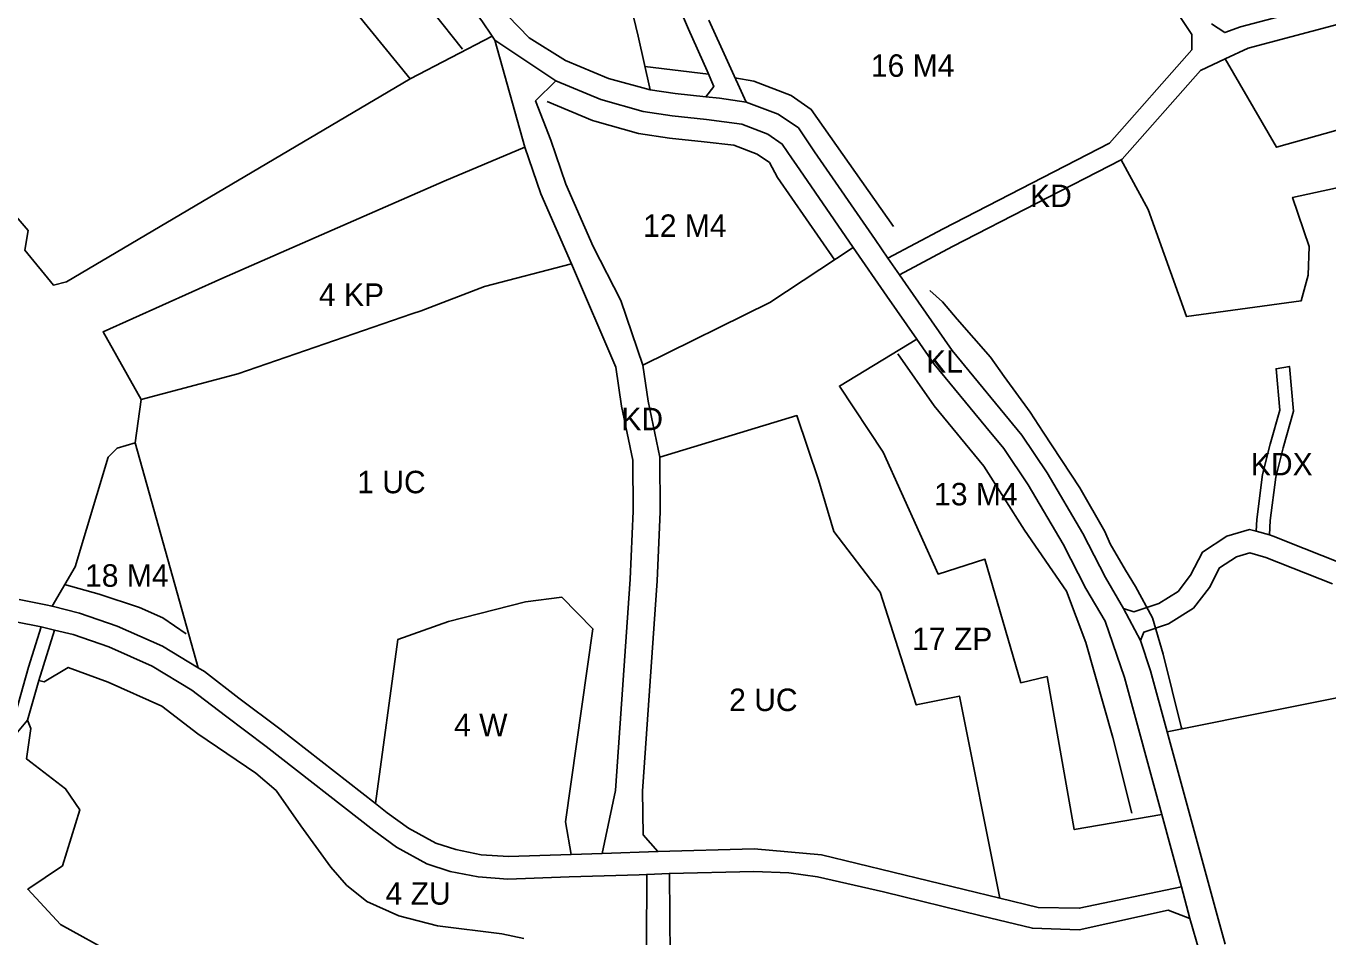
# Model space of a CAD drawing. Extents: x 7437831 to 7440315, y 5545798 to 5547888.
# Drawn here: x 7439385 to 7439964, y 5546851 to 5547256 of the extents above; entities that cross this region are included whole.
import ezdxf

# ---------------------------------------------------------------- set-up
doc = ezdxf.new("R2010")
doc.units = 0
for name, color, linetype in [('linie_rozgraniczajace', 7, 'Continuous'), ('linie_zabudowy_nieprzekraczalne', 7, 'Continuous'), ('oznaczenia_przeznaczen', 7, 'Continuous')]:
    doc.layers.add(name, color=color, linetype=linetype)

msp = doc.modelspace()

# ---------------------------------------------------------------- linework, layer by layer
at = {"layer": 'linie_rozgraniczajace'}
for points in [[(7439721.65, 5547203.82), (7439715.2, 5547208.23), (7439703.63, 5547212.64), (7439687.89, 5547214.81), (7439672.7, 5547216.33), (7439659.7, 5547218.31), (7439640.95, 5547223.59), (7439620.79, 5547231.98), (7439593.65, 5547250.12), (7439592.45, 5547251.78), (7439587.97, 5547258.66), (7439572.92, 5547278.45), (7439537.42, 5547327.35), (7439521.84, 5547350.29), (7439476.68, 5547412.41), (7439450.29, 5547445.41), (7439431.75, 5547471.05), (7439420.51, 5547489.6), (7439410.65, 5547514.06), (7439404.34, 5547535.78), (7439402.31, 5547543.75), (7439398.38, 5547559.18), (7439395.54, 5547573.5), (7439401.86, 5547591.35)], [(7439640.75, 5547321.64), (7439657.53, 5547251.88), (7439662.79, 5547227.95), (7439644.24, 5547233.06), (7439625.08, 5547241.02), (7439608.97, 5547251.12), (7439599.56, 5547260.93)], [(7439671.52, 5547274.57), (7439679.85, 5547254.99), (7439688.17, 5547236.45), (7439691.12, 5547229.44), (7439687.54, 5547224.9), (7439673.95, 5547226.25), (7439662.79, 5547227.95), (7439657.53, 5547251.88), (7439640.75, 5547321.64)], [(7439689.01, 5547258.99), (7439705.56, 5547222.46), (7439693.72, 5547224.28), (7439687.54, 5547224.9), (7439691.12, 5547229.44), (7439688.17, 5547236.45), (7439679.85, 5547254.99), (7439671.52, 5547274.57)], [(7439891.86, 5547270.85), (7439903.96, 5547252.55), (7439903.9, 5547245.77), (7439867.23, 5547204.26), (7439793.21, 5547166.14), (7439768.63, 5547153.08), (7439762.91, 5547161.37), (7439736.04, 5547200.29), (7439728.88, 5547210.98), (7439719.87, 5547217.15), (7439705.56, 5547222.46), (7439689.01, 5547258.99)], [(7439997.61, 5547264.78), (7439929.04, 5547246.52), (7439918.81, 5547241.72), (7439907.74, 5547236.53), (7439872.86, 5547197.03), (7439872.49, 5547196.85), (7439797.39, 5547158.17), (7439773.78, 5547145.63), (7439768.63, 5547153.08), (7439793.21, 5547166.14), (7439867.23, 5547204.26), (7439903.9, 5547245.77), (7439903.96, 5547252.55), (7439891.86, 5547270.85)], [(7439995.02, 5547274.44), (7439925.61, 5547255.95), (7439918.53, 5547253.45), (7439912.61, 5547257.28)], [(7439912.61, 5547257.28), (7439918.53, 5547253.45), (7439925.61, 5547255.95), (7439995.02, 5547274.44)], [(7439994.44, 5547217.29), (7439941.63, 5547202.42), (7439918.81, 5547241.72), (7439929.04, 5547246.52), (7439997.61, 5547264.78)], [(7439599.56, 5547260.93), (7439608.97, 5547251.12), (7439625.08, 5547241.02), (7439644.24, 5547233.06), (7439662.79, 5547227.95), (7439673.95, 5547226.25), (7439687.54, 5547224.9), (7439693.72, 5547224.28), (7439705.56, 5547222.46), (7439719.87, 5547217.15), (7439728.88, 5547210.98), (7439736.04, 5547200.29), (7439762.91, 5547161.37), (7439768.63, 5547153.08), (7439773.78, 5547145.63), (7439776.44, 5547141.77), (7439797.25, 5547111.91), (7439828.22, 5547074.28), (7439839.5, 5547057.41), (7439855.38, 5547030.53), (7439865.48, 5547010.81), (7439873.54, 5546997.1), (7439881.01, 5546982.86), (7439885.5, 5546969.4), (7439892.92, 5546942.17), (7439915.58, 5546858.94), (7439918.8, 5546847.65)], [(7439368.08, 5547186.09), (7439386.01, 5547165.4), (7439384.59, 5547156.64), (7439397.35, 5547140.99), (7439403.12, 5547142.44), (7439556.07, 5547232.92), (7439592.45, 5547251.78), (7439593.65, 5547250.12), (7439606.98, 5547202.45), (7439571.14, 5547187.31), (7439521.23, 5547165.56), (7439472.15, 5547143.97), (7439419.37, 5547120.24), (7439436.36, 5547090.06), (7439433.56, 5547070.86), (7439425.57, 5547068.38), (7439421.68, 5547064.4), (7439406.97, 5547015.65), (7439396.67, 5546998.07), (7439393.87, 5546998.67), (7439382.07, 5547001.08)], [(7440059.38, 5547204.07), (7439948.78, 5547180.1), (7439956.16, 5547158.18), (7439955.68, 5547145.43), (7439952.64, 5547134.07), (7439901.52, 5547127), (7439884.54, 5547174.62), (7439872.49, 5547196.85), (7439872.86, 5547197.03), (7439907.74, 5547236.53), (7439918.81, 5547241.72), (7439941.63, 5547202.42), (7439994.44, 5547217.29)], [(7439907.31, 5546844.22), (7439903.09, 5546859.16), (7439899.28, 5546873.14), (7439890.52, 5546905.32), (7439873.9, 5546966.35), (7439865.29, 5546991.42), (7439856.71, 5547005.99), (7439846.62, 5547025.71), (7439831.04, 5547052.09), (7439820.19, 5547068.29), (7439812.18, 5547077.96), (7439789.27, 5547105.87), (7439781.57, 5547116.92), (7439768.22, 5547136.07), (7439753.22, 5547157.81), (7439727.77, 5547194.66), (7439726.04, 5547197.26), (7439721.65, 5547203.82)], [(7439969.62, 5547017.51), (7439953.87, 5547023.73), (7439940.11, 5547029.33), (7439938.41, 5547029.81), (7439938.83, 5547036.19), (7439941.23, 5547055.55), (7439944.61, 5547068.63), (7439949.1, 5547084.88), (7439947.31, 5547104.81), (7439941.38, 5547103.8), (7439943.03, 5547085.43), (7439938.81, 5547070.17), (7439935.33, 5547056.67), (7439932.86, 5547036.76), (7439932.5, 5547031.45), (7439929.55, 5547032.27), (7439919.55, 5547029.25), (7439908.63, 5547022.19), (7439903.33, 5547011.86), (7439897.78, 5547004.72), (7439889.26, 5546999.35), (7439878.13, 5546995.63), (7439873.54, 5546997.1), (7439865.48, 5547010.81), (7439855.38, 5547030.53), (7439839.5, 5547057.41), (7439828.22, 5547074.28), (7439797.25, 5547111.91), (7439776.44, 5547141.77), (7439773.78, 5547145.63), (7439797.39, 5547158.17), (7439872.49, 5547196.85), (7439884.54, 5547174.62), (7439901.52, 5547127), (7439952.64, 5547134.07), (7439955.68, 5547145.43), (7439956.16, 5547158.18), (7439948.78, 5547180.1), (7440059.38, 5547204.07)], [(7439966.48, 5547007.99), (7439936.88, 5547019.85), (7439929.67, 5547021.86), (7439923.79, 5547020.08), (7439916.3, 5547015.24), (7439911.8, 5547006.46), (7439904.59, 5546997.2), (7439893.58, 5546990.24), (7439882.62, 5546986.58), (7439881.01, 5546982.86), (7439873.54, 5546997.1), (7439878.13, 5546995.63), (7439889.26, 5546999.35), (7439897.78, 5547004.72), (7439903.33, 5547011.86), (7439908.63, 5547022.19), (7439919.55, 5547029.25), (7439929.55, 5547032.27), (7439932.5, 5547031.45), (7439938.41, 5547029.81), (7439940.11, 5547029.33), (7439953.87, 5547023.73), (7439969.62, 5547017.51)], [(7440044.56, 5546972.61), (7439892.92, 5546942.17), (7439885.5, 5546969.4), (7439881.01, 5546982.86), (7439882.62, 5546986.58), (7439893.58, 5546990.24), (7439904.59, 5546997.2), (7439911.8, 5547006.46), (7439916.3, 5547015.24), (7439923.79, 5547020.08), (7439929.67, 5547021.86), (7439936.88, 5547019.85), (7439966.48, 5547007.99)], [(7439382.07, 5547001.08), (7439393.87, 5546998.67), (7439396.67, 5546998.07), (7439408.88, 5546995.06), (7439425.56, 5546989.29), (7439445.77, 5546980.27), (7439461.66, 5546970.72), (7439464.55, 5546968.98), (7439479.81, 5546957.2), (7439498.01, 5546943.52), (7439540.65, 5546910.21), (7439545.83, 5546906.16), (7439555.27, 5546899.25), (7439567.42, 5546892.61), (7439576.35, 5546889.75), (7439587.63, 5546887.5), (7439599.71, 5546886.63), (7439627.65, 5546887.63), (7439641.52, 5546888.06), (7439666.25, 5546888.85), (7439709.13, 5546890.06), (7439739.03, 5546887.5), (7439818.43, 5546868.16), (7439835.56, 5546863.99), (7439853.79, 5546863.67), (7439899.28, 5546873.14), (7439903.09, 5546859.16), (7439893.4, 5546862.8), (7439853.75, 5546854.09), (7439832.98, 5546854.74), (7439810.08, 5546860.26), (7439766.68, 5546871.01), (7439737.25, 5546877.65), (7439724.55, 5546879.39), (7439709.04, 5546880.05), (7439671.37, 5546879.16), (7439661.34, 5546878.71), (7439657.91, 5546878.56), (7439626.85, 5546877.6), (7439599.53, 5546876.62), (7439586.29, 5546877.57), (7439573.84, 5546880.06), (7439563.46, 5546883.38), (7439549.9, 5546890.79), (7439539.8, 5546898.19), (7439491.92, 5546935.58), (7439473.76, 5546949.25), (7439458.9, 5546960.71), (7439441.14, 5546971.38), (7439421.89, 5546979.98), (7439406.07, 5546985.45), (7439397.68, 5546987.47), (7439391.83, 5546988.88), (7439380.51, 5546991.19)], [(7439380.51, 5546991.19), (7439391.83, 5546988.88), (7439386.11, 5546970.9), (7439380.33, 5546950.3)], [(7439380.33, 5546950.3), (7439386.11, 5546970.9), (7439391.83, 5546988.88), (7439397.68, 5546987.47), (7439390.7, 5546965.05), (7439385.76, 5546947.44), (7439381.22, 5546942.02)], [(7439606.57, 5546850.24), (7439596.81, 5546852.25), (7439568.14, 5546855.86), (7439551.02, 5546860.31), (7439536.79, 5546866.66), (7439527.75, 5546873.86), (7439520.72, 5546881.95), (7439507.29, 5546900.3), (7439496.35, 5546916.12), (7439487.36, 5546923.82), (7439461.49, 5546941.3), (7439445.56, 5546953.62), (7439421.54, 5546964.22), (7439403.83, 5546970.85), (7439393.13, 5546964.47), (7439390.7, 5546965.05), (7439397.68, 5546987.47), (7439406.07, 5546985.45), (7439421.89, 5546979.98), (7439441.14, 5546971.38), (7439458.9, 5546960.71), (7439473.76, 5546949.25), (7439491.92, 5546935.58), (7439539.8, 5546898.19), (7439549.9, 5546890.79), (7439563.46, 5546883.38), (7439573.84, 5546880.06), (7439586.29, 5546877.57), (7439599.53, 5546876.62), (7439626.85, 5546877.6), (7439657.91, 5546878.56), (7439661.34, 5546878.71), (7439661, 5546816.56)], [(7439390.7, 5546965.05), (7439393.13, 5546964.47), (7439403.83, 5546970.85), (7439421.54, 5546964.22), (7439445.56, 5546953.62), (7439461.49, 5546941.3), (7439487.36, 5546923.82), (7439496.35, 5546916.12), (7439507.29, 5546900.3), (7439520.72, 5546881.95), (7439527.75, 5546873.86), (7439536.79, 5546866.66), (7439551.02, 5546860.31), (7439568.14, 5546855.86), (7439596.81, 5546852.25), (7439606.57, 5546850.24)], [(7439918.8, 5546847.65), (7439915.58, 5546858.94), (7439892.92, 5546942.17), (7440044.56, 5546972.61)], [(7439486.82, 5546785.36), (7439478.44, 5546804.23), (7439450.21, 5546815.29), (7439431.59, 5546839.56), (7439424.64, 5546843.02), (7439400.36, 5546856.35), (7439385.83, 5546872.11), (7439401.24, 5546882.58), (7439408.98, 5546907.43), (7439402.67, 5546916.88), (7439385.28, 5546930.1), (7439387.21, 5546943.73), (7439385.76, 5546947.44), (7439390.7, 5546965.05)], [(7439381.22, 5546942.02), (7439385.76, 5546947.44), (7439387.21, 5546943.73), (7439385.28, 5546930.1), (7439402.67, 5546916.88), (7439408.98, 5546907.43), (7439401.24, 5546882.58), (7439385.83, 5546872.11), (7439400.36, 5546856.35), (7439424.64, 5546843.02), (7439431.59, 5546839.56), (7439450.21, 5546815.29), (7439478.44, 5546804.23), (7439486.82, 5546785.36), (7439486.23, 5546779.85), (7439466.03, 5546783.83), (7439443.54, 5546786.77), (7439407.4, 5546817.11), (7439388.08, 5546823.63), (7439382.15, 5546831.69)], [(7439661, 5546816.56), (7439661.34, 5546878.71), (7439671.37, 5546879.16), (7439671.77, 5546841.75)], [(7439671.77, 5546841.75), (7439671.37, 5546879.16), (7439709.04, 5546880.05), (7439724.55, 5546879.39), (7439737.25, 5546877.65), (7439766.68, 5546871.01), (7439810.08, 5546860.26), (7439832.98, 5546854.74), (7439853.75, 5546854.09), (7439893.4, 5546862.8), (7439903.09, 5546859.16), (7439907.31, 5546844.22)]]:
    msp.add_lwpolyline(points, dxfattribs=at)
for points in [[(7439380.63, 5547586.73), (7439395.54, 5547573.5), (7439398.38, 5547559.18), (7439402.31, 5547543.75), (7439391.54, 5547533.89), (7439367.76, 5547502.29), (7439407.73, 5547414.82), (7439556.07, 5547232.92), (7439403.12, 5547142.44), (7439397.35, 5547140.99), (7439384.59, 5547156.64), (7439386.01, 5547165.4), (7439368.08, 5547186.09), (7439340.2, 5547206.42), (7439325.09, 5547222.17), (7439296.32, 5547254.08), (7439269.71, 5547290.21), (7439250.62, 5547346.08), (7439230.35, 5547407.55), (7439221.74, 5547433.66), (7439210.84, 5547476.54), (7439207.87, 5547510.17), (7439190.23, 5547565.03), (7439189.02, 5547572.47)], [(7439402.31, 5547543.75), (7439404.34, 5547535.78), (7439410.65, 5547514.06), (7439420.51, 5547489.6), (7439431.75, 5547471.05), (7439450.29, 5547445.41), (7439476.68, 5547412.41), (7439521.84, 5547350.29), (7439537.42, 5547327.35), (7439572.92, 5547278.45), (7439587.97, 5547258.66), (7439592.45, 5547251.78), (7439556.07, 5547232.92), (7439407.73, 5547414.82), (7439367.76, 5547502.29), (7439391.54, 5547533.89)], [(7439593.65, 5547250.12), (7439620.79, 5547231.98), (7439611.86, 5547223.11), (7439618.61, 5547205.53), (7439625.31, 5547185.98), (7439637.53, 5547158.25), (7439649.82, 5547134.14), (7439659.52, 5547105.34), (7439661.91, 5547089.3), (7439667.19, 5547064.45), (7439667.31, 5547040.16), (7439665.97, 5547009.44), (7439659.45, 5546915.71), (7439659.75, 5546896.34), (7439666.25, 5546888.85), (7439641.52, 5546888.06), (7439647.44, 5546916.03), (7439653.99, 5547010.11), (7439655.31, 5547040.39), (7439655.19, 5547063.16), (7439650.09, 5547087.17), (7439647.51, 5547104.57), (7439627.78, 5547150.53), (7439614.12, 5547181.6), (7439606.98, 5547202.45)], [(7439620.79, 5547231.98), (7439640.95, 5547223.59), (7439659.7, 5547218.31), (7439672.7, 5547216.33), (7439687.89, 5547214.81), (7439703.63, 5547212.64), (7439715.2, 5547208.23), (7439721.65, 5547203.82), (7439726.04, 5547197.26), (7439727.77, 5547194.66), (7439753.22, 5547157.81), (7439716.15, 5547133.24), (7439659.52, 5547105.34), (7439649.82, 5547134.14), (7439637.53, 5547158.25), (7439625.31, 5547185.98), (7439618.61, 5547205.53), (7439611.86, 5547223.11)], [(7439606.98, 5547202.45), (7439614.12, 5547181.6), (7439627.78, 5547150.53), (7439589.04, 5547140.34), (7439560.84, 5547129.57), (7439556.73, 5547128.28), (7439479.32, 5547101.57), (7439436.36, 5547090.06), (7439419.37, 5547120.24), (7439472.15, 5547143.97), (7439521.23, 5547165.56), (7439571.14, 5547187.31)], [(7439753.22, 5547157.81), (7439768.22, 5547136.07), (7439781.57, 5547116.92), (7439747.05, 5547096.07), (7439766.52, 5547066.64), (7439790.98, 5547012.39), (7439811.82, 5547019.01), (7439827.87, 5546964.02), (7439839.49, 5546966.8), (7439851.55, 5546898.69), (7439890.52, 5546905.32), (7439899.28, 5546873.14), (7439853.79, 5546863.67), (7439835.56, 5546863.99), (7439818.43, 5546868.16), (7439800.45, 5546958.11), (7439781.23, 5546954.18), (7439765.2, 5547004.33), (7439744.57, 5547031.35), (7439737.75, 5547054.35), (7439728.13, 5547082.97), (7439667.19, 5547064.45), (7439661.91, 5547089.3), (7439659.52, 5547105.34), (7439716.15, 5547133.24)], [(7439627.78, 5547150.53), (7439647.51, 5547104.57), (7439650.09, 5547087.17), (7439655.19, 5547063.16), (7439655.31, 5547040.39), (7439653.99, 5547010.11), (7439647.44, 5546916.03), (7439641.52, 5546888.06), (7439627.65, 5546887.63), (7439625.11, 5546902.12), (7439637.36, 5546987.97), (7439623.51, 5547002.16), (7439607.36, 5547000.03), (7439573.03, 5546991.26), (7439550.48, 5546983.21), (7439540.65, 5546910.21), (7439498.01, 5546943.52), (7439479.81, 5546957.2), (7439464.55, 5546968.98), (7439461.66, 5546970.72), (7439433.56, 5547070.86), (7439436.36, 5547090.06), (7439479.32, 5547101.57), (7439556.73, 5547128.28), (7439560.84, 5547129.57), (7439589.04, 5547140.34)], [(7439781.57, 5547116.92), (7439789.27, 5547105.87), (7439812.18, 5547077.96), (7439820.19, 5547068.29), (7439831.04, 5547052.09), (7439846.62, 5547025.71), (7439856.71, 5547005.99), (7439865.29, 5546991.42), (7439873.9, 5546966.35), (7439890.52, 5546905.32), (7439851.55, 5546898.69), (7439839.49, 5546966.8), (7439827.87, 5546964.02), (7439811.82, 5547019.01), (7439790.98, 5547012.39), (7439766.52, 5547066.64), (7439747.05, 5547096.07)], [(7439932.86, 5547036.76), (7439935.33, 5547056.67), (7439938.81, 5547070.17), (7439943.03, 5547085.43), (7439941.38, 5547103.8), (7439947.31, 5547104.81), (7439949.1, 5547084.88), (7439944.61, 5547068.63), (7439941.23, 5547055.55), (7439938.83, 5547036.19), (7439938.41, 5547029.81), (7439932.5, 5547031.45)], [(7439728.13, 5547082.97), (7439737.75, 5547054.35), (7439744.57, 5547031.35), (7439765.2, 5547004.33), (7439781.23, 5546954.18), (7439800.45, 5546958.11), (7439818.43, 5546868.16), (7439739.03, 5546887.5), (7439709.13, 5546890.06), (7439666.25, 5546888.85), (7439659.75, 5546896.34), (7439659.45, 5546915.71), (7439665.97, 5547009.44), (7439667.31, 5547040.16), (7439667.19, 5547064.45)], [(7439433.56, 5547070.86), (7439461.66, 5546970.72), (7439445.77, 5546980.27), (7439425.56, 5546989.29), (7439408.88, 5546995.06), (7439396.67, 5546998.07), (7439406.97, 5547015.65), (7439421.68, 5547064.4), (7439425.57, 5547068.38)], [(7439540.65, 5546910.21), (7439550.48, 5546983.21), (7439573.03, 5546991.26), (7439607.36, 5547000.03), (7439623.51, 5547002.16), (7439637.36, 5546987.97), (7439625.11, 5546902.12), (7439627.65, 5546887.63), (7439599.71, 5546886.63), (7439587.63, 5546887.5), (7439576.35, 5546889.75), (7439567.42, 5546892.61), (7439555.27, 5546899.25), (7439545.83, 5546906.16)]]:
    msp.add_lwpolyline(points, close=True, dxfattribs=at)
at = {"layer": 'linie_zabudowy_nieprzekraczalne'}
for points in [[(7439579.34, 5547246.12), (7439566.04, 5547262.64), (7439535.41, 5547306.94), (7439517.66, 5547331.6), (7439486.5, 5547375.43), (7439472.16, 5547396.12), (7439441.63, 5547437.13), (7439420.89, 5547463.48), (7439412.5, 5547475.89), (7439406.96, 5547485.33), (7439390.88, 5547531.96)], [(7439660.52, 5547238.28), (7439688.87, 5547234.92)], [(7439700.57, 5547233.25), (7439709.04, 5547231.84), (7439725.52, 5547225.4), (7439734.53, 5547219.23), (7439771.14, 5547167.05)], [(7439616.95, 5547222.75), (7439637.11, 5547214.36)], [(7439637.11, 5547214.36), (7439638.24, 5547213.97)], [(7439638.24, 5547213.97), (7439657.59, 5547208.51), (7439671.45, 5547206.4), (7439686.9, 5547204.86)], [(7439686.9, 5547204.86), (7439700.07, 5547203.29)], [(7439700.07, 5547203.29), (7439710.53, 5547199.31), (7439716, 5547195.56)], [(7439716, 5547195.56), (7439719.54, 5547188.98)], [(7439719.54, 5547188.98), (7439744.99, 5547152.13)], [(7439787.3, 5547138.56), (7439792.87, 5547133.52), (7439799.44, 5547125.88), (7439814.24, 5547109.03), (7439820.42, 5547100.33), (7439831.91, 5547084.43), (7439837.68, 5547075.54), (7439854.04, 5547050.86), (7439865.23, 5547031.32), (7439867.58, 5547025.8), (7439874.42, 5547014.21), (7439878.84, 5547006.87), (7439886.34, 5546992.89), (7439891.21, 5546976.79), (7439899.18, 5546944.37), (7439899.57, 5546943.36)], [(7439868.69, 5546939.59), (7439856.75, 5546981.95), (7439848.07, 5547004.82), (7439829.39, 5547031.97), (7439811.39, 5547060.43), (7439789.25, 5547087.35), (7439773.11, 5547110.51)], [(7439402.17, 5547007.77), (7439417.66, 5547003.4), (7439435.52, 5546997.48), (7439445.98, 5546992.89), (7439456.3, 5546985.8)], [(7439877.24, 5546905.95), (7439868.69, 5546939.59)]]:
    msp.add_lwpolyline(points, dxfattribs=at)

# ---------------------------------------------------------------- texts
at = {"layer": 'oznaczenia_przeznaczen'}
for s, p in [('16 M4', (7439761.0705, 5547233.76)), ('KD', (7439831.9227, 5547175.77)), ('12 M4', (7439659.6705, 5547162.49)), ('4 KP', (7439515.4153, 5547131.79)), ('KL', (7439785.6698, 5547102.07)), ('KD', (7439650.0027, 5547076.45)), ('KDX', (7439930.1943, 5547056.33)), ('1 UC', (7439532.4596, 5547048.38)), ('13 M4', (7439789.2205, 5547043)), ('18 M4', (7439411.3305, 5547006.76)), ('17 ZP', (7439779.4283, 5546978.54)), ('2 UC', (7439697.9796, 5546951.43)), ('4 W', (7439575.5743, 5546940.23)), ('4 ZU', (7439545.0853, 5546865.25))]:
    msp.add_text(s, height=10, dxfattribs=at).set_placement(p)

doc.saveas('drawing.dxf')
